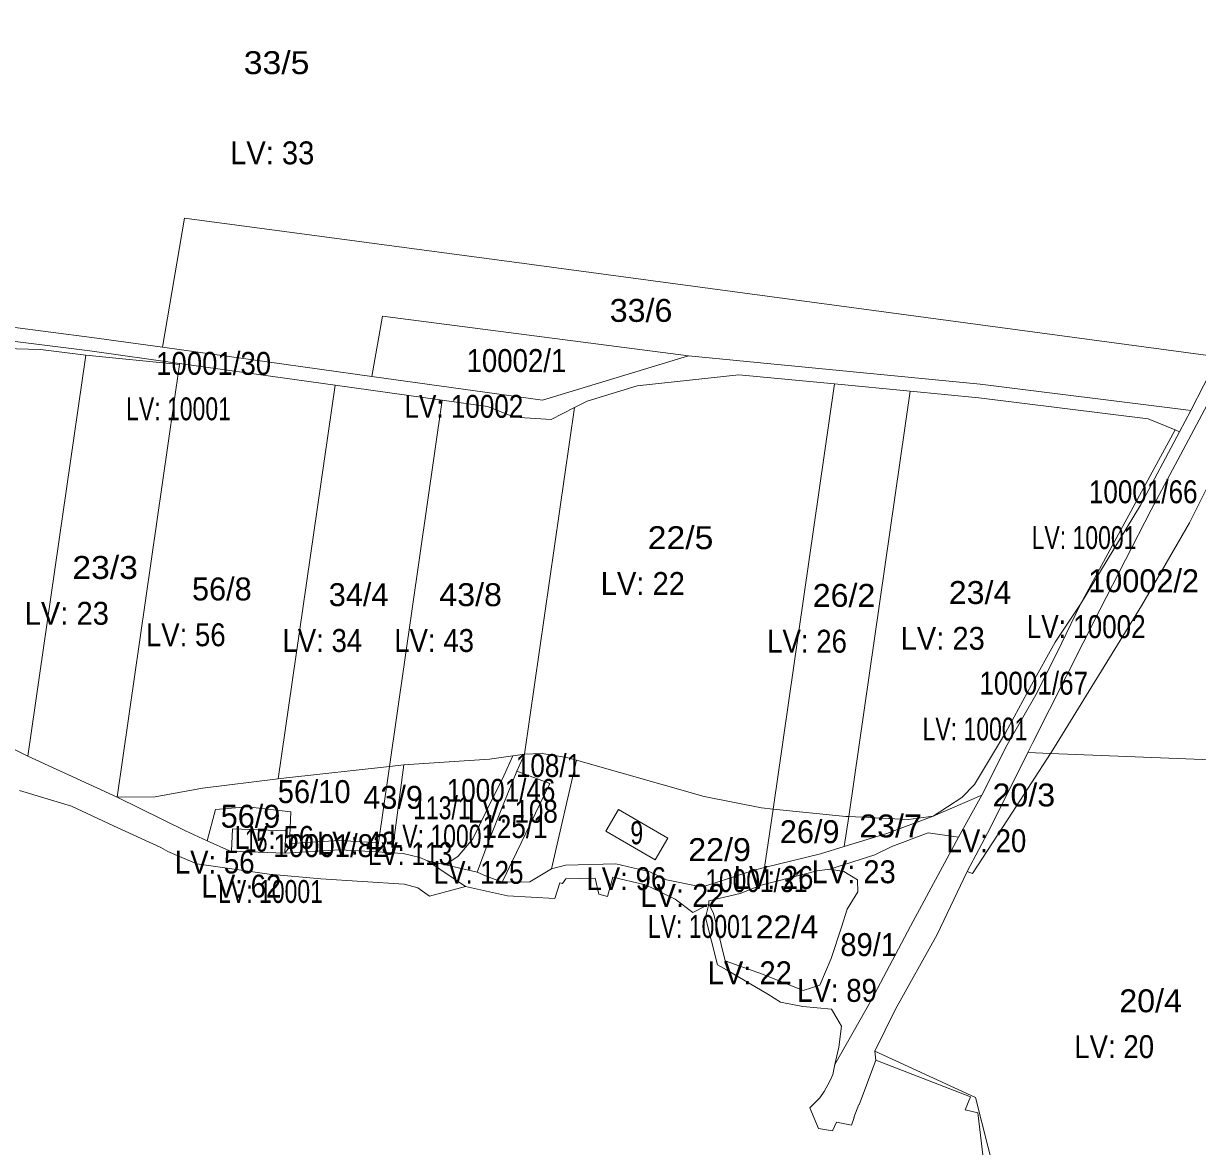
# Model space of a CAD drawing. Extents: x -713758 to -711119, y -1123067 to -1120789.
# Drawn here: x -712347 to -711834, y -1122687 to -1122197 of the extents above; entities that cross this region are included whole.
import ezdxf
from ezdxf.enums import TextEntityAlignment as Align

# ---------------------------------------------------------------- set-up
doc = ezdxf.new("R2010")
doc.units = 0
doc.header["$LTSCALE"] = 4
doc.layers.add('10', color=7, linetype='Continuous', lineweight=13)
doc.layers.add('11', color=7, linetype='Continuous')
doc.layers.add('13', color=7, linetype='Continuous')

msp = doc.modelspace()

# ---------------------------------------------------------------- linework, layer by layer
at = {"layer": '10'}
for points in [[(-711748.73, -1122189.21), (-711756.25, -1122209.29), (-711790.84, -1122275.82), (-711811.42, -1122315.11), (-711825.23, -1122342.57), (-711975.57, -1122322.4), (-712125.91, -1122302.23), (-712276.25, -1122282.06), (-712285.91, -1122338.46), (-712316.81, -1122334.14), (-712352.47, -1122329.56)], [(-712353.76, -1122335.44), (-712317.59, -1122340.09), (-712278.46, -1122345.56), (-712210.63, -1122355.03), (-712163.85, -1122361.57), (-712144.04, -1122364.34), (-712132.34, -1122369.02), (-712116.28, -1122369.96), (-712106.14, -1122364.77), (-712100.66, -1122361.97), (-712078.77, -1122355.33), (-712034.41, -1122350.43), (-711992.65, -1122354.48), (-711959.63, -1122357.67), (-711929.78, -1122360.56), (-711855.78, -1122369.76), (-711844.11, -1122374.54), (-711842.19, -1122375.32), (-711837.26, -1122366.02), (-711839.35, -1122365.76), (-711929.12, -1122354.6), (-712056.43, -1122342.27), (-712120.14, -1122361.62), (-712194.64, -1122351.21), (-712285.91, -1122338.46), (-712316.81, -1122334.14), (-712352.47, -1122329.56)], [(-712356.28, -1122511.16), (-712344.67, -1122516.97), (-712319.38, -1122341.98), (-712339.17, -1122339.5), (-712365.63, -1122338.66)], [(-711831.51, -1122355.06), (-711837.26, -1122366.02), (-711842.19, -1122375.32), (-711859.17, -1122407.31), (-711885.29, -1122450.54), (-711893.66, -1122467.8), (-711904.32, -1122489.16), (-711917.36, -1122511.94), (-711928.43, -1122533.97), (-711938.63, -1122552.27), (-711959.55, -1122591.11), (-711976.53, -1122623.28), (-711992.49, -1122651.47), (-711993.43, -1122655.81), (-711994.71, -1122658.78), (-711997.27, -1122663.3), (-711999.13, -1122666.03), (-712001.64, -1122668.67), (-712003.48, -1122670.36), (-711999.65, -1122679.4), (-711993.53, -1122680.43), (-711991.84, -1122676.58), (-711985.32, -1122678), (-711984.05, -1122674.61), (-711984.23, -1122674.54), (-711982.1, -1122668.98), (-711981.95, -1122669.03), (-711974.63, -1122649.6), (-711975.15, -1122645.71), (-711966.02, -1122627.33), (-711947.94, -1122594.74), (-711934.86, -1122567.27), (-711924.65, -1122548.11), (-711908.34, -1122515.33), (-711906.19, -1122511), (-711876.86, -1122453.09), (-711854.46, -1122409.42), (-711826.6, -1122357.07)], [(-712348.25, -1122531.87), (-712325.6, -1122538.69), (-712307.25, -1122547.3), (-712286.71, -1122556.75), (-712283.59, -1122558.55), (-712275.45, -1122561.99), (-712270.94, -1122563.9), (-712239.37, -1122568.47), (-712216.76, -1122570.52), (-712180.43, -1122572.81), (-712174.56, -1122574.35), (-712169.43, -1122578.01), (-712153.68, -1122573.83), (-712170.26, -1122562.58), (-712173.6, -1122561.08), (-712180.83, -1122559.38), (-712185.77, -1122559.09), (-712192.25, -1122558.71), (-712208.54, -1122557.75), (-712232.51, -1122559.24), (-712255.76, -1122558.39), (-712256.7, -1122558.3), (-712266.41, -1122553.87), (-712275.93, -1122549.53), (-712305.71, -1122534.77), (-712344.67, -1122516.97), (-712356.28, -1122511.16)], [(-711825.18, -1122746.95), (-711850.37, -1122745.1), (-711858.79, -1122742.93), (-711880.82, -1122735.21), (-711897.89, -1122728.87), (-711912.45, -1122721.22), (-711920.37, -1122708.38), (-711931.14, -1122665.93), (-711975.15, -1122645.71), (-711966.02, -1122627.33), (-711947.94, -1122594.74), (-711934.86, -1122567.27), (-711932.45, -1122568.1), (-711914.97, -1122541.31), (-711898.41, -1122515.73), (-711721.48, -1122522.77)], [(-711825.18, -1122746.95), (-711850.37, -1122745.1), (-711858.79, -1122742.93), (-711880.82, -1122735.21), (-711897.89, -1122728.87), (-711912.45, -1122721.22), (-711920.37, -1122708.38), (-711931.14, -1122665.93), (-711975.15, -1122645.71), (-711974.63, -1122649.6), (-711933.42, -1122665.59), (-711935.68, -1122671.26), (-711930.08, -1122672.58), (-711926.82, -1122700.64), (-711935.71, -1122722.45), (-711908.21, -1122734.05), (-711892.24, -1122742.54), (-711882.27, -1122747.05), (-711869.63, -1122752.59), (-711852.47, -1122755.55), (-711833.73, -1122755.85)]]:
    msp.add_lwpolyline(points, dxfattribs=at)
for points in [[(-712285.91, -1122338.46), (-712276.25, -1122282.06), (-712125.91, -1122302.23), (-711975.57, -1122322.4), (-711825.23, -1122342.57), (-711831.51, -1122355.06), (-711837.26, -1122366.02), (-711839.35, -1122365.76), (-711929.12, -1122354.6), (-712056.43, -1122342.27), (-712189.95, -1122324.89), (-712194.64, -1122351.21)], [(-712489, -1122331.34), (-712451.14, -1122337.71), (-712414.73, -1122347.45), (-712393.34, -1122348.2), (-712365.63, -1122338.66), (-712339.17, -1122339.5), (-712319.38, -1122341.98), (-712278.52, -1122346.01), (-712278.46, -1122345.56), (-712317.59, -1122340.09), (-712353.76, -1122335.44), (-712488.88, -1122318.12)], [(-712194.64, -1122351.21), (-712120.14, -1122361.62), (-712056.43, -1122342.27), (-712189.95, -1122324.89)], [(-712344.67, -1122516.97), (-712319.38, -1122341.98), (-712278.52, -1122346.01), (-712305.71, -1122534.77)], [(-712305.71, -1122534.77), (-712278.52, -1122346.01), (-712278.46, -1122345.56), (-712210.63, -1122355.03), (-712235.37, -1122526.78), (-712268.41, -1122530.83), (-712289.08, -1122534.7)], [(-711908.34, -1122515.33), (-711906.19, -1122511), (-711876.86, -1122453.09), (-711854.46, -1122409.42), (-711826.6, -1122357.07), (-711822, -1122352.93), (-711814.7, -1122349.21), (-711804.85, -1122349.26), (-711837.82, -1122415.02), (-711858.74, -1122451.35), (-711896.67, -1122513.04), (-711898.41, -1122515.73)], [(-712127.98, -1122515.97), (-712106.14, -1122364.77), (-712100.66, -1122361.97), (-712078.77, -1122355.33), (-712034.41, -1122350.43), (-711992.65, -1122354.48), (-712019.52, -1122540.03), (-712024.48, -1122539.53), (-712049.61, -1122534.56), (-712105.28, -1122518.72), (-712109.62, -1122517.48), (-712120.27, -1122515.76)], [(-711898.41, -1122515.73), (-711896.67, -1122513.04), (-711858.74, -1122451.35), (-711837.82, -1122415.02), (-711804.85, -1122349.26), (-711781.6, -1122352.87), (-711715.62, -1122364.24), (-711643.19, -1122376.47), (-711648.03, -1122389.42), (-711652.39, -1122401.55), (-711666.77, -1122437.7), (-711678.35, -1122460.76), (-711693.66, -1122485.02), (-711721.48, -1122522.77)], [(-712235.37, -1122526.78), (-712210.63, -1122355.03), (-712163.85, -1122361.57), (-712186.87, -1122521.41), (-712231.87, -1122526.35)], [(-712019.52, -1122540.03), (-711992.65, -1122354.48), (-711959.63, -1122357.67), (-711986.51, -1122543.29), (-711987.7, -1122543.23)], [(-711986.51, -1122543.29), (-711959.63, -1122357.67), (-711929.78, -1122360.56), (-711855.78, -1122369.76), (-711844.11, -1122374.54), (-711885.29, -1122450.54), (-711896.42, -1122467.2), (-711906.76, -1122485.78), (-711918.02, -1122506.75), (-711931.66, -1122529.27), (-711937.13, -1122535.01), (-711949.58, -1122543.1), (-711960.57, -1122544.53)], [(-712186.87, -1122521.41), (-712163.85, -1122361.57), (-712144.04, -1122364.34), (-712132.34, -1122369.02), (-712116.28, -1122369.96), (-712106.14, -1122364.77), (-712127.98, -1122515.97), (-712133.09, -1122516.71), (-712143.19, -1122518.18), (-712180.61, -1122520.72)], [(-711885.29, -1122450.54), (-711859.17, -1122407.31), (-711842.19, -1122375.32), (-711844.11, -1122374.54)], [(-711949.58, -1122543.1), (-711928.43, -1122533.97), (-711917.36, -1122511.94), (-711904.32, -1122489.16), (-711893.66, -1122467.8), (-711885.29, -1122450.54), (-711896.42, -1122467.2), (-711906.76, -1122485.78), (-711918.02, -1122506.75), (-711931.66, -1122529.27), (-711937.13, -1122535.01)], [(-712185.77, -1122559.09), (-712180.61, -1122520.72), (-712143.19, -1122518.18), (-712133.09, -1122516.71), (-712137.02, -1122525.44), (-712144.73, -1122541.1), (-712150.45, -1122552.95), (-712156.9, -1122560.61), (-712162.49, -1122564.29), (-712170.26, -1122562.58), (-712173.6, -1122561.08), (-712180.83, -1122559.38)], [(-712162.49, -1122564.29), (-712148.62, -1122567.59), (-712143.81, -1122554.64), (-712137, -1122537.36), (-712131.24, -1122523.43), (-712127.98, -1122515.97), (-712133.09, -1122516.71), (-712137.02, -1122525.44), (-712144.73, -1122541.1), (-712150.45, -1122552.95), (-712156.9, -1122560.61)], [(-712137.64, -1122571.94), (-712116.94, -1122528.82), (-712131.24, -1122523.43), (-712127.98, -1122515.97), (-712120.27, -1122515.76), (-712109.62, -1122517.48), (-712105.28, -1122518.72), (-712116.24, -1122566.12), (-712125.7, -1122571.77)], [(-711934.86, -1122567.27), (-711924.65, -1122548.11), (-711908.34, -1122515.33), (-711898.41, -1122515.73), (-711914.97, -1122541.31), (-711932.45, -1122568.1)], [(-712305.71, -1122534.77), (-712289.08, -1122534.7), (-712268.41, -1122530.83), (-712235.37, -1122526.78), (-712231.87, -1122526.35), (-712186.87, -1122521.41), (-712191.67, -1122554.72), (-712208.55, -1122553.74), (-712230.44, -1122555.1), (-712229.92, -1122541.22), (-712248.78, -1122539.07), (-712262.82, -1122540.26), (-712266.41, -1122553.87), (-712275.93, -1122549.53)], [(-712192.25, -1122558.71), (-712185.77, -1122559.09), (-712180.61, -1122520.72), (-712186.87, -1122521.41), (-712191.67, -1122554.72)], [(-712116.24, -1122566.12), (-712105.28, -1122518.72), (-712049.61, -1122534.56), (-712024.48, -1122539.53), (-712019.52, -1122540.03), (-712023.21, -1122565.53), (-712027.77, -1122566.64), (-712049.28, -1122573.67), (-712052.28, -1122573.6), (-712066.01, -1122570.82), (-712073.22, -1122567.33), (-712088.14, -1122563.89), (-712110.08, -1122564.42)], [(-712148.62, -1122567.59), (-712143.81, -1122554.64), (-712137, -1122537.36), (-712131.24, -1122523.43), (-712116.94, -1122528.82), (-712137.64, -1122571.94), (-712145, -1122569.18)], [(-712170.26, -1122562.58), (-712153.68, -1122573.83), (-712135.42, -1122577.83), (-712114.66, -1122578.98), (-712112.6, -1122572.14), (-712111.41, -1122572.48), (-712109.93, -1122570.42), (-712097.12, -1122570.11), (-712095.46, -1122577.12), (-712091.72, -1122578.21), (-712089.39, -1122569.76), (-712075.84, -1122572.88), (-712073, -1122574.1), (-712062.23, -1122579.32), (-712054.54, -1122585.11), (-712053.6, -1122584.64), (-712047.49, -1122581.56), (-712047.51, -1122580.08), (-712033.91, -1122576.79), (-712024.74, -1122573.22), (-712000.19, -1122566.92), (-711994.7, -1122566.24), (-711975.16, -1122559.99), (-711967.69, -1122556.34), (-711951.83, -1122550.36), (-711938.63, -1122552.27), (-711928.43, -1122533.97), (-711949.58, -1122543.1), (-711969.81, -1122550.73), (-711988.41, -1122556.41), (-711998.78, -1122559.57), (-712023.21, -1122565.53), (-712027.77, -1122566.64), (-712049.28, -1122573.67), (-712052.28, -1122573.6), (-712066.01, -1122570.82), (-712073.22, -1122567.33), (-712088.14, -1122563.89), (-712110.08, -1122564.42), (-712116.24, -1122566.12), (-712125.7, -1122571.77), (-712137.64, -1122571.94), (-712145, -1122569.18), (-712148.62, -1122567.59), (-712162.49, -1122564.29)], [(-712266.41, -1122553.87), (-712262.82, -1122540.26), (-712248.78, -1122539.07), (-712229.92, -1122541.22), (-712230.44, -1122555.1), (-712230.49, -1122556.51), (-712232.51, -1122559.24), (-712232.13, -1122549.55), (-712255.41, -1122548.62), (-712255.76, -1122558.39), (-712256.7, -1122558.3)], [(-712092.41, -1122549.71), (-712070.92, -1122562.18), (-712065.37, -1122552.72), (-712086.92, -1122540.15)], [(-712092.41, -1122549.71), (-712070.92, -1122562.18), (-712065.37, -1122552.72), (-712086.92, -1122540.15)], [(-712023.21, -1122565.53), (-712019.52, -1122540.03), (-711987.7, -1122543.23), (-711986.51, -1122543.29), (-711988.41, -1122556.41), (-711998.78, -1122559.57)], [(-711988.41, -1122556.41), (-711986.51, -1122543.29), (-711960.57, -1122544.53), (-711949.58, -1122543.1), (-711969.81, -1122550.73)], [(-712255.76, -1122558.39), (-712232.51, -1122559.24), (-712232.13, -1122549.55), (-712255.41, -1122548.62)], [(-712232.51, -1122559.24), (-712208.54, -1122557.75), (-712192.25, -1122558.71), (-712191.67, -1122554.72), (-712208.55, -1122553.74), (-712230.44, -1122555.1), (-712230.49, -1122556.51)], [(-712049.02, -1122587.32), (-712043.76, -1122607.92), (-712039.85, -1122610.2), (-712021.73, -1122620.72), (-712016.2, -1122624.26), (-712006.54, -1122626.18), (-711994.04, -1122627.4), (-711991.68, -1122631.32), (-711989.7, -1122634.82), (-711990.86, -1122643.91), (-711992.49, -1122651.47), (-711976.53, -1122623.28), (-711959.55, -1122591.11), (-711938.63, -1122552.27), (-711951.83, -1122550.36), (-711967.69, -1122556.34), (-711975.16, -1122559.99), (-711994.7, -1122566.24), (-711988.55, -1122567.22), (-711982.66, -1122570.86), (-711982.55, -1122576.17), (-711987.13, -1122583.74), (-711989.68, -1122591.53), (-711994.12, -1122605.16), (-711999.16, -1122616.81), (-712006.31, -1122619.15), (-712024.07, -1122612.07), (-712040.43, -1122606.26), (-712045.5, -1122585.5), (-712047.49, -1122581.56)], [(-712047.51, -1122580.08), (-712047.49, -1122581.56), (-712045.5, -1122585.5), (-712040.43, -1122606.26), (-712024.07, -1122612.07), (-712006.31, -1122619.15), (-711999.16, -1122616.81), (-711994.12, -1122605.16), (-711989.68, -1122591.53), (-711987.13, -1122583.74), (-711982.55, -1122576.17), (-711982.66, -1122570.86), (-711988.55, -1122567.22), (-711994.7, -1122566.24), (-712000.19, -1122566.92), (-712024.74, -1122573.22), (-712033.91, -1122576.79)]]:
    msp.add_lwpolyline(points, close=True, dxfattribs=at)

# ---------------------------------------------------------------- texts
at = {"layer": '11'}
for s, width, p in [('33/5', 1.1, (-712236.12, -1122219.25)), ('33/6', 1.05, (-712077.101, -1122327.38)), ('10002/1', 0.9, (-712131.471, -1122349.26)), ('10001/30', 0.9, (-712263.61, -1122350.5)), ('10001/66', 0.85, (-711857.981, -1122406.53)), ('22/5', 1.1, (-712059.87, -1122426.57)), ('23/3', 1.1, (-712310.941, -1122439.57)), ('43/8', 1.05, (-712151.47, -1122451.44)), ('26/2', 1.05, (-711988.541, -1122451.75)), ('23/4', 1.05, (-711929.179, -1122450.5)), ('10001/67', 0.85, (-711905.77, -1122490.07)), ('108/1', 0.85, (-712117.48, -1122526.01)), ('56/10', 0.95, (-712219.721, -1122537.38)), ('10001/46', 0.85, (-712138.181, -1122536.83)), ('20/3', 1.05, (-711910.07, -1122538.85)), ('113/1', 0.75, (-712164.01, -1122544.45)), ('125/1', 0.85, (-712132.12, -1122552.63)), ('23/7', 1.05, (-711968.231, -1122552.37)), ('15', 0.65, (-712244.98, -1122558.62)), ('9', 0.75, (-712078.971, -1122555.37)), ('10001/82', 0.9, (-712212.46, -1122560.97)), ('22/9', 1.05, (-712042.831, -1122562.7)), ('10001/31', 0.8, (-712026.74, -1122576.24)), ('22/4', 1.05, (-712013.431, -1122596.44)), ('89/1', 0.95, (-711977.77, -1122604.14)), ('20/4', 1.05, (-711854.76, -1122628.68))]:
    msp.add_text(s, height=10, dxfattribs=dict(at, width=width)).set_placement(p, align=Align.CENTER)
for s, p in [('10002/2', (-711857.82, -1122445.38)), ('56/8', (-712260.02, -1122448.94)), ('34/4', (-712200.35, -1122451.44)), ('43/9', (-712185.28, -1122539.88)), ('56/9', (-712247.51, -1122548.13)), ('26/9', (-712003.53, -1122554.87))]:
    msp.add_text(s, height=10, dxfattribs=at).set_placement(p, align=Align.CENTER)
at = {"layer": '13'}
for s, width, p in [('LV: 33 ', 0.95, (-712236.265, -1122258.63)), ('LV: 10002 ', 0.85, (-712152.818, -1122369.26)), ('LV: 10001 ', 0.75, (-712277.535, -1122370.33)), ('LV: 10001 ', 0.75, (-711882.406, -1122426.53)), ('LV: 22 ', 0.95, (-712074.559, -1122446.57)), ('LV: 23 ', 0.95, (-712325.897, -1122459.57)), ('LV: 10002 ', 0.85, (-711881.276, -1122465.38)), ('LV: 56 ', 0.9, (-712274.074, -1122468.94)), ('LV: 34 ', 0.9, (-712214.505, -1122471.44)), ('LV: 43 ', 0.9, (-712165.725, -1122471.44)), ('LV: 26 ', 0.9, (-712002.996, -1122471.75)), ('LV: 23 ', 0.95, (-711943.701, -1122470.5)), ('LV: 10001 ', 0.75, (-711929.995, -1122510.07)), ('LV: 108 ', 0.85, (-712131.432, -1122546.01)), ('LV: 56 ', 0.9, (-712235.514, -1122557.38)), ('LV: 10001 ', 0.75, (-712162.606, -1122556.83)), ('LV: 20 ', 0.9, (-711924.726, -1122558.85)), ('LV: 43 ', 0.9, (-712199.434, -1122559.88)), ('LV: 56 ', 0.9, (-712261.463, -1122568.13)), ('LV: 113 ', 0.8, (-712176.39, -1122564.45)), ('LV: 125 ', 0.85, (-712146.408, -1122572.63)), ('LV: 23 ', 0.95, (-711982.552, -1122572.37)), ('LV: 62 ', 0.9, (-712249.798, -1122578.62)), ('LV: 96 ', 0.9, (-712081.848, -1122575.37)), ('LV: 26 ', 0.9, (-712017.617, -1122574.87)), ('LV: 10001 ', 0.75, (-712237.388, -1122580.97)), ('LV: 22 ', 0.95, (-712057.285, -1122582.7)), ('LV: 10001 ', 0.75, (-712049.861, -1122596.24)), ('LV: 22 ', 0.95, (-712027.885, -1122616.44)), ('LV: 89 ', 0.9, (-711989.882, -1122624.14)), ('LV: 20 ', 0.9, (-711868.981, -1122648.68))]:
    msp.add_text(s, height=10, dxfattribs=dict(at, width=width)).set_placement(p, align=Align.CENTER)

doc.saveas('drawing.dxf')
